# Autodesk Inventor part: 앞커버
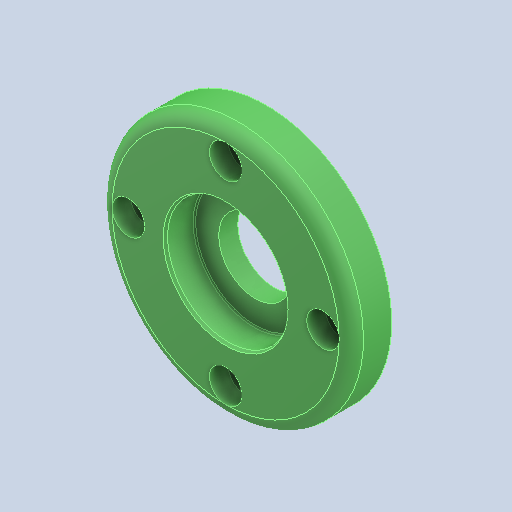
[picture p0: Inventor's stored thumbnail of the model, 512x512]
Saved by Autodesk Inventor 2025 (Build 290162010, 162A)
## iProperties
Created: 2024-07
Part Number: 앞커버
Material: 알루미늄 6061
Document SubType Name: Modeling
Designer: 학생
Density: 2.71 g/cm^3
Appearance: 기본값
Author: jhkim
Sending System: Autodesk Inventor 2025
Preprocessor: ST-DEVELOPER v20
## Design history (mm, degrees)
feature "솔리드1"
node "솔리드2"
